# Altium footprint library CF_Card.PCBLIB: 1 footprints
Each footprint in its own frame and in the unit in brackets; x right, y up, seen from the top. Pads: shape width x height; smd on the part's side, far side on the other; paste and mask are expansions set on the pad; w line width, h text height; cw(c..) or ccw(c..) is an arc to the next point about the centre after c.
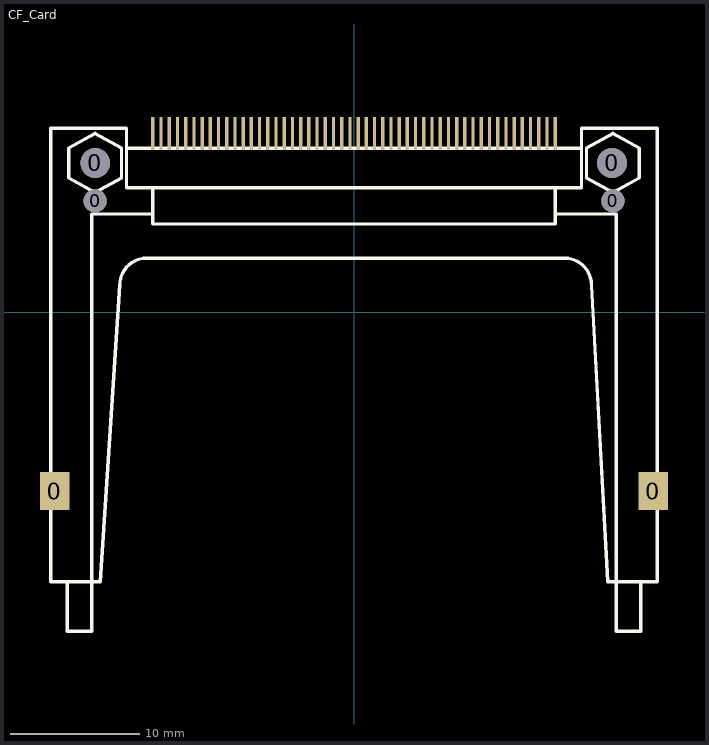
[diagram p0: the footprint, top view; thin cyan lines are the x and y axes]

## CF_Card [mil]
pads (56):
  rect 90x115 smd: 0(-907.5,-542.5) 0(907.5,-542.5)
  round 70 hole 70: 0(-785,337.5) 0(785,337.5)
  round 90 hole 90: 0(-785,452.5) 0(782.5,452.5)
  rect 10x100 smd: 1(-610,542.5) 2(-585.1,542.5) 3(-560.2,542.5) 4(-535.3,542.5) 5(-510.4,542.5) 6(-485.5,542.5) 7(-460.6,542.5) 8(-435.7,542.5) 9(-410.8,542.5) 10(-385.9,542.5) 11(-361,542.5) 12(-336.1,542.5) 13(-311.2,542.5) 14(-286.3,542.5) 15(-261.4,542.5) 16(-236.5,542.5) 17(-211.6,542.5) 18(-186.7,542.5) 19(-161.8,542.5) 20(-136.9,542.5) 21(-112,542.5) 22(-87.1,542.5) 23(-62.2,542.5) 24(-37.3,542.5) 25(-12.4,542.5) 26(12.5,542.5) 27(37.4,542.5) 28(62.3,542.5) 29(87.2,542.5) 30(112.1,542.5) 31(137,542.5) 32(161.9,542.5) 33(186.8,542.5) 34(211.7,542.5) 35(236.6,542.5) 36(261.5,542.5) 37(286.4,542.5) 38(311.3,542.5) 39(336.2,542.5) 40(361.1,542.5) 41(386,542.5) 42(410.9,542.5) 43(435.8,542.5) 44(460.7,542.5) 45(485.6,542.5) 46(510.5,542.5) 47(535.4,542.5) 48(560.3,542.5) 49(585.2,542.5) 50(610.1,542.5)
Top Overlay:
  lines w10: -870,-817.5 -870,-967.5 -795,-967.5 -795,-817.5 ; -610,297.5 -795,297.5 -795,-817.5 ; -610,377.5 -610,267.5 610,267.5 610,377.5 ; 610,297.5 795,297.5 795,-817.5 ; 870,-817.5 870,-967.5 795,-967.5 795,-817.5 ; -795,-817.5 -770,-817.5 -710.12,82.5 cw(c-628.72,82.5) -630.06,163.88 639.94,163.88 cw(c638.61,82.5) 720,82.5 770,-817.5 795,-817.5 ; -795,-817.5 -920,-817.5 -920,557.5 -690,557.5 -690,497.5 ; -690,497.5 -690,377.5 690,377.5 690,497.5 ; -690,497.5 690,497.5 ; 690,497.5 690,557.5 920,557.5 920,-817.5 795,-817.5 ; -865,407.5 -865,497.5 -785,542.5 -705,497.5 -705,407.5 -785,362.5 -865,407.5 ; 705,407.5 785,362.5 865,407.5 865,497.5 785,542.5 705,497.5 705,407.5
